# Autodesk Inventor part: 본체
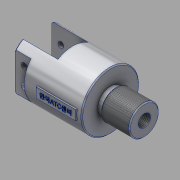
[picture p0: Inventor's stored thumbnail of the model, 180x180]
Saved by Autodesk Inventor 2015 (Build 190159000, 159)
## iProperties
Created: 2019-02
Part Number: 본체
Material: 알루미늄 6061
Document SubType Name: Modeling
Designer: SCD-A18
Density: 2.7 g/cm^3
Appearance: 알루미늄 - 평지
Author: SCD-A18
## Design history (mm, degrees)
sketch "스케치1"
  geometry: L1 (-54, 0)-(54, 0); L2 (-54, 0)-(-54, 29); L3 (-54, 29)-(20, 29); L4 (20, 29)-(20, 13); L5 (20, 13)-(25, 13); L6 (25, 13)-(25, 15); L7 (25, 15)-(54, 15); L8 (54, 15)-(54, 0); 2 further points
  constraints: 16 end point, 4 perpendicular, 2 vertical, 1 coincident, 1 horizontal, 1 midpoint, 1 parallel
  dimensions: "d0" = 108 distance of L1.start L1.end; "d3" = 30 diameter of L7 L1; "d4" = 26 diameter of L5 L1; "d5" = 58 diameter of L3 L1; "d6" = 74 distance of L2.end L3.end; "d7" = 5 distance of L4.end L5.end
revolve "회전1" sketch "스케치1" stored, may be unused: angle "d8" = 90 deg
sketch "스케치2"
  geometry: L1 (54, 29)-(54, -29) reference; L2 (54, -29)-(-20, -29) reference; L3 (-20, -29)-(-20, -13) reference; L4 (-20, -13)-(-25, -13) reference; L5 (-25, -13)-(-25, -15) reference; L6 (-25, -15)-(-54, -15) reference; L7 (-54, -15)-(-54, 15) reference; L8 (-54, 15)-(-25, 15) reference; L9 (-25, 15)-(-25, 13) reference; L10 (-25, 13)-(-20, 13) reference; L11 (-20, 13)-(-20, 29) reference; L12 (-20, 29)-(54, 29) reference; L13 (54, 15)-(18, 15); L14 (18, 15)-(18, -15); L15 (18, -15)-(54, -15); L16 (54, -15)-(54, 15); L17 (54, 0)-(101.402, 0); L18 (54, 29)-(38, 29); L19 (38, 29)-(38, 22); L20 (38, 22)-(54, 22); L21 (54, 22)-(54, 29); L22 (38, -29)-(38, -22); L23 (38, -22)-(54, -22); L24 (54, -29)-(38, -29); L25 (54, -22)-(54, -29); 1 further point
  constraints: 26 end point, 4 parallel, 3 horizontal, 3 symmetric about line, 2 midpoint, 2 perpendicular
  dimensions: "d9" = 36 distance of L15.end L14.end; "d10" = 30 distance of L14.end L13.end; "d13" = 16 distance of L19.end L20.end; "d14" = 44 distance between parallel lines of L23 L20
extrude "돌출1" cut sketch "스케치2" stored distance "d11" = 113.5; taper "d12" = 0 deg
chamfer "모따기1" distance "d15" = 1; stored, may be unused: second distance "d16" = 2, angle "d17" = 45 deg
chamfer "모따기2" distance "d18" = 1; stored, may be unused: second distance "d19" = 2, angle "d20" = 45 deg
feature "스레드1" dims "d21" = 10, "d22" = 0
sketch "스케치3"
  geometry: L1 (20, -29)-(-18, -29) reference; L2 (-18, -29)-(-18, 29) reference; L3 (-18, 29)-(20, 29) reference; L4 (20, 29)-(20, 13) reference; L5 (20, 13)-(25, 13) reference; L6 (25, 13)-(25, 14) reference; L7 (25, 14)-(26, 15) reference; L8 (26, 15)-(53, 15) reference; L9 (53, 15)-(54, 14) reference; L10 (54, 14)-(54, -14) reference; L11 (54, -14)-(53, -15) reference; L12 (53, -15)-(26, -15) reference; L13 (26, -15)-(25, -14) reference; L14 (25, -14)-(25, -13) reference; L15 (25, -13)-(20, -13) reference; L16 (20, -13)-(20, -29) reference; L17 (-18, 14)-(-15.35, 14); L18 (-15.35, 14)-(-15.35, 17); L19 (-15.35, 17)-(-10.65, 17); L20 (-10.65, 17)-(-10.65, 14); L21 (-10.65, 14)-(-6.35, 14); L22 (-6.35, 14)-(-6.35, 17); L23 (-6.35, 17)-(-1.65, 17); L24 (-1.65, 17)-(-1.65, 14); L25 (-1.65, 14)-(2, 14); L26 (2, 14)-(2, 16); L27 (2, 16)-(9, 16); L28 (9, 16)-(9, 4); L29 (9, 4)-(54, 4); L30 (-18, 0)-(81.486, 0); L31 (-18, 14)-(-18, 0); L32 (-18, -24.819)-(-18, 24.819) reference; L33 (54, 4)-(54, 0); L34 (54, 0)-(-18, 0); L35 (-13, 17)-(-13, 30.361); L36 (-4, 17)-(-4, 31.286); 1 further point
  constraints: 38 end point, 10 point on line, 9 perpendicular, 5 midpoint, 3 horizontal, 2 vertical, 1 collinear
  dimensions: "d23" = 4.7 distance between parallel lines of L20 L18; "d24" = 4.7 distance of L22.end L23.end; "d25" = 34 diameter of L19 L30; "d26" = 28 diameter of L17 L30; "d27" = 5 distance from line of L35 L2.end; "d28" = 9 distance from line of L36 L35.end; "d29" = 32 diameter of L27 L30; "d30" = 20 distance between parallel lines of L2 L26; "d31" = 27 distance between parallel lines of L2 L28; "d32" = 8 diameter of L29 L30
revolve "회전2" sketch "스케치3" stored, may be unused: angle "d33" = 90 deg
hole "구멍1" diameter "d36" = 12.376; stored, may be unused: countersink angle "d40" = 90 deg, drill point angle "d42" = 120 deg; dims "d37" = 18, "d38" = 4, "d39" = 2, "d41" = 22, "d62" = 10, "d63" = 10
chamfer "모따기3" distance "d43" = 1; stored, may be unused: second distance "d44" = 2, angle "d45" = 45 deg
fillet "모깎기1" dims "d46" = 0.8
sketch "스케치4"
  geometry: L1 (54, -14)-(53, -15) reference; L2 (53, -15)-(26, -15) reference; L3 (26, -15)-(25, -14) reference; L4 (25, -14)-(25, -13) reference; L5 (25, -13)-(20, -13) reference; L6 (20, -13)-(20, -29) reference; L7 (20, -29)-(-18, -29) reference; L8 (-18, -29)-(-18, -15) reference; L9 (-18, -15)-(-17, -14) reference; L10 (-17, -14)-(-15.35, -14) reference; L11 (-15.35, -14)-(-15.35, -16.2) reference; L12 (-14.55, -17)-(-11.45, -17) reference; L13 (-10.65, -16.2)-(-10.65, -14) reference; L14 (-10.65, -14)-(-6.35, -14) reference; L15 (-6.35, -14)-(-6.35, -16.2) reference; L16 (-5.55, -17)-(-2.45, -17) reference; L17 (-1.65, -16.2)-(-1.65, -14) reference; L18 (-1.65, -14)-(2, -14) reference; L19 (2, -14)-(2, -16) reference; L20 (2, -16)-(9, -16) reference; L21 (9, -16)-(9, -4) reference; L22 (9, -4)-(30.737, -4) reference; L23 (30.737, -4)-(32, -6.188) reference; L24 (32, -6.188)-(54, -6.188) reference; L25 (54, -6.188)-(54, -14) reference; L26 (53, 15)-(54, 14) reference; L27 (54, 14)-(54, 6.188) reference; L28 (54, 6.188)-(32, 6.188) reference; L29 (32, 6.188)-(30.737, 4) reference; L30 (30.737, 4)-(9, 4) reference; L31 (9, 4)-(9, 16) reference; L32 (9, 16)-(2, 16) reference; L33 (2, 16)-(2, 14) reference; L34 (2, 14)-(-1.65, 14) reference; L35 (-1.65, 14)-(-1.65, 16.2) reference; L36 (-2.45, 17)-(-5.55, 17) reference; L37 (-6.35, 16.2)-(-6.35, 14) reference; L38 (-6.35, 14)-(-10.65, 14) reference; L39 (-10.65, 14)-(-10.65, 16.2) reference; L40 (-11.45, 17)-(-14.55, 17) reference; L41 (-15.35, 16.2)-(-15.35, 14) reference; L42 (-15.35, 14)-(-17, 14) reference; L43 (-17, 14)-(-18, 15) reference; L44 (-18, 15)-(-18, 29) reference; L45 (-18, 29)-(20, 29) reference; L46 (20, 29)-(20, 13) reference; L47 (20, 13)-(25, 13) reference; L48 (25, 13)-(25, 14) reference; L49 (25, 14)-(26, 15) reference; L50 (26, 15)-(53, 15) reference; L51 (-53, 24.819)-(-18, 24.819) reference; L52 (-54, -23.643)-(-54, 23.643) reference; L53 (-18, -24.819)-(-53, -24.819) reference; L54 (-45, 9)-(-45, -9); C1 r 3 at (-45, 9); C2 r 3 at (-45, -9); A1 r 0.8 centre (-14.55, -16.2) between (-15.35, -16.2) and (-14.55, -17) reference; A2 r 0.8 centre (-11.45, -16.2) between (-11.45, -17) and (-10.65, -16.2) reference; A3 r 0.8 centre (-5.55, -16.2) between (-6.35, -16.2) and (-5.55, -17) reference; A4 r 0.8 centre (-2.45, -16.2) between (-2.45, -17) and (-1.65, -16.2) reference; A5 r 0.8 centre (-2.45, 16.2) between (-1.65, 16.2) and (-2.45, 17) reference; A6 r 0.8 centre (-5.55, 16.2) between (-5.55, 17) and (-6.35, 16.2) reference; A7 r 0.8 centre (-11.45, 16.2) between (-10.65, 16.2) and (-11.45, 17) reference; A8 r 0.8 centre (-14.55, 16.2) between (-14.55, 17) and (-15.35, 16.2) reference; 2 further points
  constraints: 2 centre point, 2 end point, 1 equal radius, 1 horizontal alignment, 1 midpoint, 1 vertical, 1 vertical alignment
  dimensions: "d47" = 9 distance from line of L54.end L52; "d48" = 6 diameter of C2; "d49" = 18 distance of L54.start L54.end
extrude "돌출2" cut sketch "스케치4" stored distance "d50" = 113.5; taper "d51" = 0 deg
node "작업 평면1"
sketch "스케치5"
  geometry: L1 (-25, 5)-(15, 5); L2 (15, 5)-(15, -5); L3 (15, -5)-(-25, -5); L4 (-25, -5)-(-25, 5); L5 (20, -29)-(20, 29) reference; 2 further points
  constraints: 8 end point, 2 parallel, 1 horizontal, 1 horizontal alignment, 1 midpoint, 1 perpendicular
  dimensions: "d53" = 5 distance between parallel lines of L5 L2; "d54" = 40 distance of L1.start L1.end; "d55" = 10 distance of L3.end L1.start
extrude "돌출3" join sketch "스케치5" stored distance "d56" = 113.5; taper "d57" = 0 deg
sketch "스케치6"
  geometry: L1 (-25, -5)-(-25, 5) reference; L2 (15, -5)-(-25, -5) reference; 2 further points
  constraints: 1 other
  dimensions: "d58" = 20 distance from line of L1 point (-5, 0); "d59" = 5 distance from line of L2 point (-5, 0)
feature "엠보싱1" sketch "스케치6" dims "d60" = 0.5, "d61" = 0
chamfer "모따기4" distance "d64" = 1; stored, may be unused: second distance "d65" = 2, angle "d66" = 45 deg
node "솔리드1"
node "절단 모서리 투영1"
node "절단 모서리 투영2"
node "절단 모서리 투영3"
